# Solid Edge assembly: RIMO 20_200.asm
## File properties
Title: Zylinder
Author: ahadarics
Template: iso metric assembly.asm
Last saved by: ahadarics
Revision: 15
Application: Solid Edge
Username: ahadarics
Dokumentum tartalom típus: 1
Document Number: RIMO 20/200
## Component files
Profilrohr.par
Kit_1.par
Kit_2.par
Kolbenstange.par
Mutter_1.par
Mutter_2.par
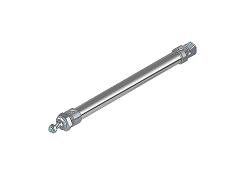
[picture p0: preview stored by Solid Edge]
